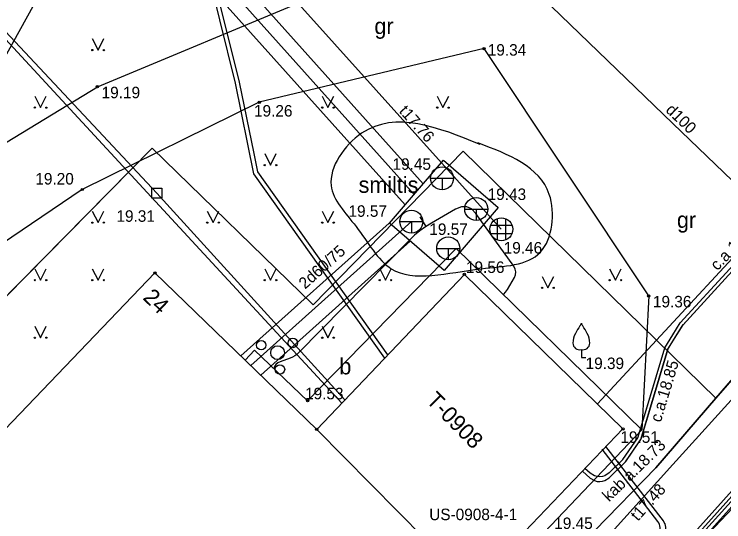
# Model space of a CAD drawing. Extents: x 532933 to 533143, y 328014 to 328163.
# Drawn here: x 532971.35 to 533002.21, y 328074.5 to 328096.56 of the extents above; entities that cross this region are included whole.
import ezdxf

# ---------------------------------------------------------------- set-up
doc = ezdxf.new("R2010")
doc.units = 0
for name, color, linetype in [('BUVE_EKAS_####_####_#', 7, 'Continuous'), ('BUVE_EKAS_ADRS_TKST_#', 7, 'Continuous'), ('CELI_CMAL_####_####_#', 7, 'Continuous'), ('CELI_CSEG_####_TKST_#', 7, 'Continuous'), ('DREN_ELEM_####_####_#', 7, 'Continuous'), ('DREN_ELEM_####_TKST_#', 7, 'Continuous'), ('DREN_VADP_####_####_#', 7, 'Continuous'), ('DREN_VADP_####_TKST_#', 7, 'Continuous'), ('ELEK_ACRL_####_####_#', 7, 'Continuous'), ('ELEK_ACRL_####_TKST_#', 7, 'Continuous'), ('ELEK_ELEM_####_####_#', 7, 'Continuous'), ('ELEK_ELEM_####_TKST_#', 7, 'Continuous'), ('ELEK_STTP_####_####_#', 7, 'Continuous'), ('ELEK_STTP_####_TKST_#', 7, 'Continuous'), ('ELEK_VADP_VSPR_####_#', 7, 'Continuous'), ('ELEK_VADP_VSPR_####_I', 7, 'Continuous'), ('ELEK_VADP_VSPR_TKST_I', 7, 'Continuous'), ('ELEK_VADP_ZSPR_####_#', 7, 'Continuous'), ('RELJ_AATZ_####_TKST_#', 7, 'Continuous'), ('RELJ_ELEM_####_####_#', 7, 'Continuous'), ('RELJ_HORZ_PAMT_####_#', 7, 'Continuous'), ('ROBZ_UZMR_####_####_#', 7, 'Continuous'), ('SAKK_KKAN_####_####_#', 7, 'Continuous'), ('SILT_ELEM_####_####_#', 7, 'Continuous'), ('SILT_ELEM_####_TKST_#', 7, 'Continuous'), ('SILT_VADP_NEDR_####_#', 7, 'Continuous'), ('SILT_VADP_NEDR_TKST_#', 7, 'Continuous'), ('SILT_VADP_UDEN_TKAM_#', 7, 'Continuous'), ('SKAN_ELEM_PAST_TKST_#', 7, 'Continuous'), ('SKAN_VADP_PAST_####_#', 7, 'Continuous'), ('SKAN_VADP_PAST_TKST_#', 7, 'Continuous'), ('TERT_ELEM_####_####_#', 7, 'Continuous'), ('TERT_IZMT_####_TKST_#', 7, 'Continuous'), ('TERT_KONT_####_####_#', 7, 'Continuous'), ('UDTK_VADP_UDEN_####_#', 7, 'Continuous'), ('UDTK_VADP_UDEN_TKST_#', 7, 'Continuous')]:
    doc.layers.add(name, color=color, linetype=linetype)

msp = doc.modelspace()

# ---------------------------------------------------------------- linework, layer by layer
at = {"layer": 'BUVE_EKAS_####_####_#'}
for p, q in [((532977.471, 328085.314), (532963.98, 328071.276)), ((532984.51, 328078.518), (532977.471, 328085.314)), ((532984.51, 328078.518), (532991.271, 328071.691))]:
    msp.add_line(p, q, dxfattribs=at)
at = {"layer": 'CELI_CMAL_####_####_#'}
msp.add_line((532981.394, 328081.526), (532981.81, 328081.956), dxfattribs=at)
for points in [[(532960.996, 328082.718), (532967.7, 328088.991), (532974.969, 328093.406), (532984.293, 328097.298), (532999.014, 328101.642), (533000, 328101.952)], [(532998.947, 328084.318), (532991.789, 328095.063), (532982.013, 328092.735), (532974.31, 328088.941), (532969.478, 328085.677), (532964.771, 328080.302), (532962.135, 328074.858), (532962.083, 328069.653)], [(532998.656, 328078.496), (532990.574, 328086.384), (532984.111, 328079.759), (532981.81, 328081.956)], [(532998.947, 328084.318), (532998.656, 328078.496)], [(532982.259, 328061.27), (532998.656, 328078.496)]]:
    msp.add_lwpolyline(points, dxfattribs=at)
at = {"layer": 'DREN_ELEM_####_####_#'}
for p, q in [((532992.07, 328087.386), (532993.006, 328087.386)), ((532992.363, 328087.679), (532992.363, 328086.743)), ((532992.713, 328087.679), (532992.713, 328086.743)), ((532992.07, 328087.036), (532993.006, 328087.036))]:
    msp.add_line(p, q, dxfattribs=at)
msp.add_circle((532992.538, 328087.211), 0.5, dxfattribs=at)
at = {"layer": 'DREN_VADP_####_####_#'}
msp.add_line((532992.538, 328087.211), (532970.198, 328112.068), dxfattribs=at)
at = {"layer": 'ELEK_ACRL_####_####_#'}
for points in [[(533000.322, 328083.149), (533002.47, 328085.498)], [(533000.433, 328083.048), (533002.581, 328085.397)], [(533000, 328082.63), (533000.322, 328083.149)], [(533000, 328082.346), (533000.449, 328083.07)], [(532999.645, 328082.058), (533000, 328082.63)], [(532999.772, 328081.979), (533000, 328082.346)], [(532998.936, 328079.691), (532999.645, 328082.058)], [(532999.08, 328079.648), (532999.789, 328082.015)], [(532998.474, 328078.148), (532998.936, 328079.691)], [(532998.618, 328078.105), (532999.08, 328079.648)], [(532997.828, 328077.209), (532998.474, 328078.148)], [(532997.952, 328077.124), (532998.598, 328078.063)]]:
    msp.add_lwpolyline(points, dxfattribs=at)
at = {"layer": 'ELEK_ELEM_####_####_#'}
msp.add_lwpolyline([(532977.78, 328088.558), (532977.333, 328088.558), (532977.333, 328088.998), (532977.78, 328088.998)], close=True, dxfattribs=at)
at = {"layer": 'ELEK_STTP_####_####_#'}
for p, q in [((532990.934, 328085.254), (532984.51, 328078.518)), ((532997.829, 328078.537), (532990.934, 328085.254)), ((532991.271, 328071.691), (532997.829, 328078.537))]:
    msp.add_line(p, q, dxfattribs=at)
at = {"layer": 'ELEK_VADP_VSPR_####_#'}
for points in [[(532999.344, 328074.52), (532996.919, 328077.656)], [(532999.585, 328074.535), (532997.077, 328077.779)], [(532997.474, 328076.938), (532997.636, 328076.729)], [(532997.602, 328077.1), (532997.769, 328076.885)]]:
    msp.add_lwpolyline(points, dxfattribs=at)
for centre in [(532998.948, 328074.214), (532999.189, 328074.23)]:
    msp.add_arc(centre, 0.5, 329.5845, 37.7118, dxfattribs=at)
at = {"layer": 'ELEK_VADP_VSPR_####_I'}
for points in [[(533000, 328082.63), (533000.322, 328083.149), (533002.47, 328085.498), (533013.203, 328096.663), (533020.765, 328104.555), (533025.03, 328108.829)], [(533000, 328082.346), (533000.442, 328083.058), (533002.579, 328085.395), (533013.311, 328096.559), (533020.872, 328104.45), (533025.042, 328108.629)], [(532997.225, 328076.624), (532997.828, 328077.209), (532998.474, 328078.148), (532999.645, 328082.058), (533000, 328082.63)], [(532997.226, 328076.416), (532997.943, 328077.112), (532998.611, 328078.082), (532999.783, 328081.996), (533000, 328082.346)], [(532996.405, 328076.402), (532996.072, 328076.704)], [(532996.404, 328076.61), (532996.175, 328076.818)], [(532997.225, 328076.624), (532997.045, 328076.503), (532996.935, 328076.468), (532996.817, 328076.454), (532996.7, 328076.464), (532996.588, 328076.496), (532996.404, 328076.61)], [(532996.405, 328076.402), (532996.589, 328076.288), (532996.701, 328076.256), (532996.818, 328076.246), (532996.936, 328076.26), (532997.046, 328076.295), (532997.226, 328076.416)]]:
    msp.add_lwpolyline(points, dxfattribs=at)
at = {"layer": 'ELEK_VADP_ZSPR_####_#'}
for p, q in [((533015.085, 328089.795), (533000, 328072.993)), ((533015.178, 328089.675), (533000, 328072.768)), ((533015.366, 328089.434), (533000, 328072.319))]:
    msp.add_line(p, q, dxfattribs=at)
for points in [[(532975.169, 328117.107), (532977.825, 328106.296), (532979.6, 328099.088), (532980.956, 328093.565), (532981.761, 328089.629), (532987.457, 328081.608)], [(532987.598, 328081.755), (532981.948, 328089.71), (532981.784, 328090.509), (532981.151, 328093.609), (532978.113, 328105.828), (532975.361, 328117.154)], [(532985.737, 328079.805), (532977.556, 328088.778), (532968.408, 328098.547), (532965.686, 328099.193)], [(532965.739, 328098.982), (532968.304, 328098.364), (532985.598, 328079.659)], [(533015.32, 328089.608), (533004.957, 328078.053), (533004.027, 328077.035), (533001.028, 328073.711), (533000, 328072.544)], [(533000, 328072.357), (533007.294, 328080.052)]]:
    msp.add_lwpolyline(points, dxfattribs=at)
at = {"layer": 'RELJ_ELEM_####_####_#'}
for centre in [(532991.789, 328095.063), (532974.969, 328093.406), (532982.013, 328092.735), (532974.31, 328088.941), (532977.471, 328085.314), (532990.934, 328085.254), (532998.947, 328084.318), (532984.111, 328079.759), (532984.51, 328078.518), (532997.829, 328078.537)]:
    msp.add_circle(centre, 0.05, dxfattribs=at)
at = {"layer": 'RELJ_HORZ_PAMT_####_#'}
msp.add_line((532988.988, 328087.75), (532989.252, 328087.326), dxfattribs=at)
for points in [[(532974.68, 328101.466), (532970.462, 328093.847)], [(532992.651, 328084.396), (532992.72, 328084.475), (532992.802, 328084.597), (532993.104, 328085.11), (532993.159, 328085.237), (532993.173, 328085.362), (532993.147, 328085.486), (532993.081, 328085.607), (532991.429, 328087.898), (532991.241, 328088.095), (532991.031, 328088.191), (532990.8, 328088.189), (532990.548, 328088.087), (532989.497, 328087.478), (532989.24, 328087.318), (532988.996, 328087.142), (532988.764, 328086.95), (532988.545, 328086.742), (532983.733, 328081.854), (532983.648, 328081.777), (532983.556, 328081.711), (532983.458, 328081.655), (532983.352, 328081.611), (532982.916, 328081.454), (532982.817, 328081.406), (532982.738, 328081.339), (532982.68, 328081.254), (532982.642, 328081.151)]]:
    msp.add_lwpolyline(points, dxfattribs=at)
at = {"layer": 'ROBZ_UZMR_####_####_#'}
for p, q in [((533025.763, 328107.492), (533001.874, 328079.871)), ((532977.358, 328090.737), (532962.791, 328075.982)), ((532984.352, 328083.929), (532977.358, 328090.737)), ((532990.879, 328090.61), (532984.352, 328083.929)), ((533001.874, 328079.871), (532990.879, 328090.61))]:
    msp.add_line(p, q, dxfattribs=at)
for points in [[(532993.949, 328071.405), (532999.253, 328076.841), (533001.874, 328079.871), (533025.763, 328107.492), (533029.138, 328104.514), (533014.917, 328088.072), (533037.903, 328068.645), (533030.421, 328036.082)], [(532954.932, 328051.068), (532962.791, 328075.982), (532977.358, 328090.737), (532984.352, 328083.929), (532990.879, 328090.61), (533001.874, 328079.871), (532999.253, 328076.841), (532993.949, 328071.405), (532979.271, 328056.364), (532968.026, 328044.841)]]:
    msp.add_lwpolyline(points, close=True, dxfattribs=at)
at = {"layer": 'SAKK_KKAN_####_####_#'}
msp.add_line((533026.568, 328111.881), (532996.716, 328079.621), dxfattribs=at)
at = {"layer": 'SILT_ELEM_####_####_#'}
for p, q in [((532989.459, 328089.428), (532989.959, 328089.428)), ((532989.959, 328089.428), (532990.459, 328089.428)), ((532989.959, 328089.428), (532989.959, 328088.928)), ((532990.947, 328088.091), (532991.447, 328088.091)), ((532991.447, 328088.091), (532991.947, 328088.091)), ((532991.447, 328088.091), (532991.447, 328087.591)), ((532988.127, 328087.544), (532988.627, 328087.544)), ((532988.627, 328087.544), (532989.127, 328087.544)), ((532988.627, 328087.544), (532988.627, 328087.044)), ((532989.729, 328086.382), (532990.229, 328086.382)), ((532990.229, 328086.382), (532990.729, 328086.382)), ((532990.229, 328086.382), (532990.229, 328085.882))]:
    msp.add_line(p, q, dxfattribs=at)
for centre in [(532989.959, 328089.428), (532991.447, 328088.091), (532988.627, 328087.544), (532990.229, 328086.382)]:
    msp.add_circle(centre, 0.5, dxfattribs=at)
at = {"layer": 'SILT_VADP_NEDR_####_#'}
for points in [[(532988.748, 328088.729), (532971.8, 328107.627)], [(532988.627, 328087.544), (532981.64, 328081.289)]]:
    msp.add_lwpolyline(points, dxfattribs=at)
at = {"layer": 'SILT_VADP_UDEN_TKAM_#'}
for points in [[(532972.841, 328107.364), (532989.142, 328089.188)], [(532988.353, 328088.27), (532971.734, 328106.801)], [(532990.022, 328090.212), (532992.404, 328088.164), (532990.05, 328085.425), (532987.668, 328087.473), (532990.022, 328090.212)], [(532981.207, 328081.707), (532987.657, 328087.482)], [(532988.574, 328086.693), (532982.072, 328080.872)]]:
    msp.add_lwpolyline(points, dxfattribs=at)
at = {"layer": 'SKAN_VADP_PAST_####_#'}
for points in [[(533018.885, 328112.548), (533015.334, 328093.891), (533000, 328076.986)], [(533000, 328076.986), (532997.194, 328073.892), (532983.572, 328058.168), (532980.848, 328060.709)]]:
    msp.add_lwpolyline(points, dxfattribs=at)
at = {"layer": 'TERT_ELEM_####_####_#'}
for p, q in [((532974.75, 328095.5), (532975, 328095)), ((532975, 328095), (532975.25, 328095.5)), ((532972.25, 328093), (532972.5, 328092.5)), ((532972.5, 328092.5), (532972.75, 328093)), ((532984.75, 328093), (532985, 328092.5)), ((532985, 328092.5), (532985.25, 328093)), ((532989.75, 328093), (532990, 328092.5)), ((532990, 328092.5), (532990.25, 328093)), ((532982.25, 328090.5), (532982.5, 328090)), ((532982.5, 328090), (532982.75, 328090.5)), ((532974.75, 328088), (532975, 328087.5)), ((532975, 328087.5), (532975.25, 328088)), ((532979.75, 328088), (532980, 328087.5)), ((532980, 328087.5), (532980.25, 328088)), ((532984.75, 328088), (532985, 328087.5)), ((532985, 328087.5), (532985.25, 328088)), ((532972.25, 328085.5), (532972.5, 328085)), ((532972.5, 328085), (532972.75, 328085.5)), ((532974.75, 328085.5), (532975, 328085)), ((532975, 328085), (532975.25, 328085.5)), ((532982.25, 328085.5), (532982.5, 328085)), ((532982.5, 328085), (532982.75, 328085.5)), ((532987.25, 328085.5), (532987.5, 328085)), ((532987.5, 328085), (532987.75, 328085.5)), ((532997.25, 328085.5), (532997.5, 328085)), ((532997.5, 328085), (532997.75, 328085.5)), ((532994.316, 328085.165), (532994.566, 328084.665)), ((532994.566, 328084.665), (532994.816, 328085.165)), ((532972.25, 328083), (532972.5, 328082.5)), ((532972.5, 328082.5), (532972.75, 328083)), ((532984.75, 328083), (532985, 328082.5)), ((532985, 328082.5), (532985.25, 328083)), ((532996.018, 328081.989), (532996.018, 328081.637)), ((532996.018, 328081.637), (532996.218, 328081.637))]:
    msp.add_line(p, q, dxfattribs=at)
for centre, radius in [((532974.75, 328095), 0.028), ((532975.25, 328095), 0.0263), ((532972.25, 328092.5), 0.028), ((532972.75, 328092.5), 0.0263), ((532984.75, 328092.5), 0.028), ((532985.25, 328092.5), 0.0263), ((532989.75, 328092.5), 0.028), ((532990.25, 328092.5), 0.0263), ((532982.25, 328090), 0.028), ((532982.75, 328090), 0.0263), ((532974.75, 328087.5), 0.028), ((532975.25, 328087.5), 0.0263), ((532979.75, 328087.5), 0.028), ((532980.25, 328087.5), 0.0263), ((532984.75, 328087.5), 0.028), ((532985.25, 328087.5), 0.0263), ((532972.25, 328085), 0.028), ((532972.75, 328085), 0.0263), ((532974.75, 328085), 0.028), ((532975.25, 328085), 0.0263), ((532982.25, 328085), 0.028), ((532982.75, 328085), 0.0263), ((532987.25, 328085), 0.028), ((532987.75, 328085), 0.0263), ((532997.25, 328085), 0.028), ((532997.75, 328085), 0.0263), ((532994.316, 328084.665), 0.028), ((532994.816, 328084.665), 0.0263), ((532972.25, 328082.5), 0.028), ((532972.75, 328082.5), 0.0263), ((532983.47, 328082.273), 0.207), ((532984.75, 328082.5), 0.028), ((532985.25, 328082.5), 0.0263), ((532982.095, 328082.172), 0.204), ((532982.809, 328081.849), 0.301), ((532982.912, 328081.121), 0.205)]:
    msp.add_circle(centre, radius, dxfattribs=at)
for centre, radius, start, end in [((532995.601, 328083.275), 0.439, 324.3837, 341.712), ((532996.435, 328083.275), 0.439, 198.288, 215.6163), ((533008.643, 328075.241), 14.88, 148.4844, 149.9901), ((532983.393, 328075.241), 14.88, 30.0099, 31.5156), ((532996.542, 328082.262), 0.89, 151.757, 179.9138), ((532995.493, 328082.262), 0.89, 0.0862, 28.243), ((532995.941, 328082.269), 0.29, 181.0782, 285.2823), ((532996.094, 328082.269), 0.29, 254.7177, 358.9218)]:
    msp.add_arc(centre, radius, start, end, dxfattribs=at)
at = {"layer": 'TERT_KONT_####_####_#'}
msp.add_spline([(532991.624, 328090.894), (532986.463, 328091.382), (532985.138, 328089.114), (532986.219, 328087.334), (532987.75, 328085.5), (532991.659, 328085.5), (532994.239, 328086.217), (532994.623, 328088.73), (532991.519, 328090.964)], degree=3, dxfattribs=at)
at = {"layer": 'UDTK_VADP_UDEN_####_#'}
for p, q in [((533000, 328091.812), (532974.279, 328116.599)), ((533010.744, 328081.458), (533000, 328091.812))]:
    msp.add_line(p, q, dxfattribs=at)

# ---------------------------------------------------------------- texts
at = {"layer": 'BUVE_EKAS_ADRS_TKST_#'}
msp.add_text('24', height=0.7, rotation=316.0067, dxfattribs=at).set_placement((532976.913, 328084.201))
at = {"layer": 'CELI_CSEG_####_TKST_#'}
for s, p in [('gr', (532987.019, 328095.695)), ('gr', (533000.176, 328087.273)), (' b', (532985.235, 328080.906))]:
    msp.add_text(s, height=0.7, dxfattribs=at).set_placement(p)
at = {"layer": 'DREN_ELEM_####_TKST_#'}
msp.add_text(' 19.46', height=0.5, dxfattribs=at).set_placement((532992.455, 328086.158))
at = {"layer": 'DREN_VADP_####_TKST_#'}
msp.add_text('t17.76', height=0.5, rotation=311.9476, dxfattribs=at).set_placement((532988.06, 328092.326))
at = {"layer": 'ELEK_ACRL_####_TKST_#'}
for s, rotation, p in [('c.a.18.58', 46.1302, (533001.933, 328085.387)), ('c.a.18.85', 73.3213, (532999.473, 328078.793))]:
    msp.add_text(s, height=0.5, rotation=rotation, dxfattribs=at).set_placement(p)
at = {"layer": 'ELEK_ELEM_####_TKST_#'}
msp.add_text('US-0908-4-1', height=0.5, dxfattribs=at).set_placement((532989.402, 328074.571))
at = {"layer": 'ELEK_STTP_####_TKST_#'}
msp.add_text('T-0908', height=0.7, rotation=314.6084, dxfattribs=at).set_placement((532989.231, 328079.727))
at = {"layer": 'ELEK_VADP_VSPR_TKST_I'}
msp.add_text('kab.a.18.73', height=0.5, rotation=44.1525, dxfattribs=at).set_placement((532997.222, 328075.347))
at = {"layer": 'RELJ_AATZ_####_TKST_#'}
for s, p in [(' 19.34', (532991.763, 328094.758)), (' 19.19', (532974.969, 328092.906)), (' 19.26', (532981.596, 328092.111)), (' 19.20', (532972.086, 328089.158)), (' 19.31', (532975.613, 328087.537)), (' 19.56', (532990.815, 328085.315)), (' 19.36', (532998.947, 328083.818)), (' 19.39', (532996.018, 328081.137)), (' 19.53', (532983.817, 328079.824)), (' 19.51', (532997.531, 328077.931))]:
    msp.add_text(s, height=0.5, dxfattribs=at).set_placement(p)
at = {"layer": 'SILT_ELEM_####_TKST_#'}
for s, p in [('19.45', (532987.806, 328089.796)), ('19.43', (532991.943, 328088.485)), ('19.57', (532985.891, 328087.754)), ('19.57', (532989.407, 328086.966))]:
    msp.add_text(s, height=0.5, dxfattribs=at).set_placement(p)
at = {"layer": 'SILT_VADP_NEDR_TKST_#'}
msp.add_text('2d60/75', height=0.5, rotation=41.8389, dxfattribs=at).set_placement((532984.001, 328084.586))
at = {"layer": 'SKAN_ELEM_PAST_TKST_#'}
msp.add_text(' 19.45', height=0.5, dxfattribs=at).set_placement((532994.654, 328074.187))
at = {"layer": 'SKAN_VADP_PAST_TKST_#'}
msp.add_text('t17.48', height=0.5, rotation=47.7895, dxfattribs=at).set_placement((532998.477, 328074.501))
at = {"layer": 'TERT_IZMT_####_TKST_#'}
msp.add_text('smiltis', height=0.7, dxfattribs=at).set_placement((532986.331, 328088.796))
at = {"layer": 'UDTK_VADP_UDEN_TKST_#'}
msp.add_text('d100', height=0.5, rotation=316.0591, dxfattribs=at).set_placement((532999.652, 328092.356))

doc.saveas('drawing.dxf')
